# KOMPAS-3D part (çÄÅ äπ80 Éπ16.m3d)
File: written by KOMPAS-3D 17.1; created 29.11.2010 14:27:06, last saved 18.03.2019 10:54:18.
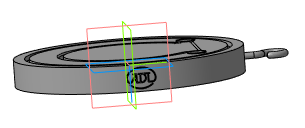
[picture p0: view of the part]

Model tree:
1. Плоскость XY
2. Плоскость ZX
3. Плоскость ZY
4. Ось X
5. Ось Y
6. Ось Z
7. Начало координат
8. Операция без истории:2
